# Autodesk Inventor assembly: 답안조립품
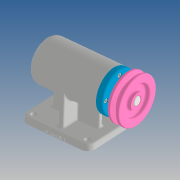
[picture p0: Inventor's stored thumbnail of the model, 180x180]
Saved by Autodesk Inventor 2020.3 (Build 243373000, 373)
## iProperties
Created: 2020-10
Part Number: 답안조립품
Document SubType Name: Assembly
Designer: EZDESIGN
Author: EZDESIGN
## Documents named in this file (12)
- C:\Users\EZDESIGN\Desktop\701004V1036\답안조립품.iam
- C:\Users\EZDESIGN\Desktop\701004V1036\V벨트풀리.ipt
- C:\Users\EZDESIGN\Desktop\701004V1036\멈춤나사 M3.ipt
- C:\Users\EZDESIGN\Desktop\701004V1036\베어링 51202.ipt
- C:\Users\EZDESIGN\Desktop\701004V1036\베어링 6004.ipt
- C:\Users\EZDESIGN\Desktop\701004V1036\본체.ipt
- C:\Users\EZDESIGN\Desktop\701004V1036\볼트 M4.ipt
- C:\Users\EZDESIGN\Desktop\701004V1036\어댑터슬리브.ipt
- C:\Users\EZDESIGN\Desktop\701004V1036\오일 실.ipt
- C:\Users\EZDESIGN\Desktop\701004V1036\축.ipt
- C:\Users\EZDESIGN\Desktop\701004V1036\커버.ipt
- C:\Users\EZDESIGN\Desktop\701004V1036\키 5 x 5 x 16.ipt
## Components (1 placed, 1 different names)
1. V벨트풀리:1
